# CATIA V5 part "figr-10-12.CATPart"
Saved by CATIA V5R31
Part number: Part1
Bounding box of the stored display mesh (mm): x -100 to 0, y -100 to 90, z 0 to 33.63
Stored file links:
  D:\PROJECTS\Project 2021\US EDITION\CATIA V5 6R 2021\Resources\Part Files\c10_catia_v5_6r2021_prt\c10_catia_v5_6r2021_prt\figr-10-12.CATPart
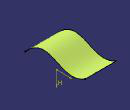
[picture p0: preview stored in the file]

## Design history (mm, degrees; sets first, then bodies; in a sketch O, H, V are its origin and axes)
Set1
  Sketch1 on face of yz-plane, origin (0, 0, 0), H (0, 0, -1), V (0, 1, 0)
    spline S1 through (0, -100) (-30, -20) (-10, 30) (-20, 90)
  Extrude1: Element1 Sketch1, Lim1 0, Lim2 100, Direction face of yz-plane
Body1 (main body)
